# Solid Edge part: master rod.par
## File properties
Author: Deepak Maini
Template: normal.par
Last saved by: Robert a Rhodes jr
Revision: 7
Application: Solid Edge
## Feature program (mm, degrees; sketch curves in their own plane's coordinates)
sketch for "unnamed Protrusion 1" #1 plane through (0, 0, 0) normal (0, 0, 1) x-axis (1, 0, 0)
  circle centre (-104.4884, 26) radius 5
sketch for "unnamed Protrusion 1" #2 plane through (0, 0, 0) normal (0, 0, 1) x-axis (1, 0, 0)
  circle centre (-50.4884, 43) radius 5
sketch for "unnamed Protrusion 1" #3 plane through (0, 0, 0) normal (0, 0, 1) x-axis (1, 0, 0)
  circle centre (-104.4884, -26) radius 5
sketch for "unnamed Protrusion 1" #4 plane through (0, 0, 0) normal (0, 0, 1) x-axis (1, 0, 0)
  circle centre (-50.4884, -43) radius 5
sketch for "unnamed Protrusion 1" #5 plane through (0, 0, 0) normal (0, 0, 1) x-axis (1, 0, 0)
  arc centre (-185.4143, 0) radius 72 from (-116.8653, -22.0235) to (-116.8653, 22.0235) ccw
  arc centre (-104.4884, 26) radius 13 from (-116.8653, 22.0235) to (-104.0399, 38.9923) cw
  arc centre (-101.5558, 110.9494) radius 72 from (-104.0399, 38.9923) to (-58.2987, 53.3923) ccw
  arc centre (-50.4884, 43) radius 13 from (-58.2987, 53.3923) to (-39.1844, 49.4202) cw
  arc centre (23.4225, 84.9783) radius 72 from (-39.1844, 49.4202) to (21.6546, 13) ccw
  line (21.6546, 13) -> (184.5116, 9)
  line (184.5116, 9) -> (184.5116, -9)
  line (184.5116, -9) -> (21.6546, -13)
  arc centre (23.4225, -84.9783) radius 72 from (-39.1844, -49.4202) to (21.6546, -13) cw
  arc centre (-50.4884, -43) radius 13 from (-58.2987, -53.3923) to (-39.1844, -49.4202) ccw
  arc centre (-101.5558, -110.9494) radius 72 from (-104.0399, -38.9923) to (-58.2987, -53.3923) cw
  arc centre (-104.4884, -26) radius 13 from (-116.8653, -22.0235) to (-104.0399, -38.9923) ccw
  dimension (linear) = 104.4884
  dimension (linear) = 104.4884
  dimension (linear) = 21.6546
extrude "unnamed Protrusion 1" add finite 40 symmetric
sketch for "unnamed Protrusion 2" plane through (0, 0, 0) normal (0, 0, 1) x-axis (1, 0, 0)
  circle centre (-65.4884, 0) radius 31.5
extrude "unnamed Protrusion 2" add finite 70 symmetric
sketch for "unnamed Cutout 1" plane through (-65.4884, 0, 35) normal (0, 0, 1) x-axis (1, 0, 0)
  circle centre (0, 0) radius 26
extrude "unnamed Cutout 1" cut through along -normal
sketch for "unnamed Cutout 2" plane through (0, 0, 0) normal (0, 0, 1) x-axis (1, 0, 0)
  arc centre (-185.4143, 0) radius 72 from (-116.8653, -22.0235) to (-116.8653, 22.0235) ccw
  arc centre (-104.4884, 26) radius 13 from (-116.8653, 22.0235) to (-104.0399, 38.9923) cw
  arc centre (-101.5558, 110.9494) radius 72 from (-104.0399, 38.9923) to (-58.2987, 53.3923) ccw
  arc centre (-50.4884, 43) radius 13 from (-58.2987, 53.3923) to (-39.1844, 49.4202) cw
  arc centre (23.4225, 84.9783) radius 72 from (-39.1844, 49.4202) to (21.6408, 13.0003) ccw
  arc centre (26.7635, 219.9485) radius 207.0115 from (21.6408, 13.0003) to (-53.3048, 29.0484) cw
  arc centre (-65.4884, 0) radius 31.5 from (-53.3064, -29.0491) to (-53.3048, 29.0484) cw
  arc centre (26.7787, -220.0192) radius 207.0826 from (21.6337, -13.0005) to (-53.3064, -29.0491) ccw
  arc centre (23.4225, -84.9783) radius 72 from (21.6337, -13.0005) to (-39.1844, -49.4202) ccw
  arc centre (-50.4884, -43) radius 13 from (-39.1844, -49.4202) to (-58.2987, -53.3923) cw
  arc centre (-101.5558, -110.9494) radius 72 from (-58.2987, -53.3923) to (-104.0399, -38.9923) ccw
  arc centre (-104.4884, -26) radius 13 from (-104.0399, -38.9923) to (-116.8653, -22.0235) cw
extrude "unnamed Cutout 2" cut finite 28 symmetric
sketch for "unnamed Cutout 3" plane through (0, 0, 0) normal (0, -1, 0) x-axis (1, 0, 0)
  line (44.7709, 14.1242) -> (184.5116, 9.0608)
  arc centre (52.2023, 91.7693) radius 78 from (21.6546, 20) to (44.7709, 14.1242) ccw
  line (20.7865, 38.9081) -> (21.6546, 20)
  line (184.5116, 38.9081) -> (20.7865, 38.9081)
  line (184.5116, 9.0608) -> (184.5116, 38.9081)
extrude "unnamed Cutout 3" cut finite 355.6 symmetric
mirror "unnamed Mirror 1" of "unnamed Cutout 3" about plane through (0, 0, 0) normal (0, 0, 1)
extrude "unnamed Cutout 4" cut finite 355.6 symmetric
sketch for "unnamed Protrusion 3" plane through (0, 0, 0) normal (0, 0, 1) x-axis (1, 0, 0)
  circle centre (184.5116, 0) radius 17.5
extrude "unnamed Protrusion 3" add finite 42 symmetric
sketch for "unnamed Cutout 5" plane through (184.5116, 0, 21) normal (0, 0, 1) x-axis (1, 0, 0)
  circle centre (0, 0) radius 12
extrude "unnamed Cutout 5" cut through along -normal
sketch for "unnamed Cutout 6" plane through (0, 0, 0) normal (0, 0, 1) x-axis (1, 0, 0)
  line (0.4837, -6) -> (150.4837, -6)
  arc centre (0.4837, 0) radius 6 from (0.4837, 6) to (0.4837, -6) ccw
  line (150.4837, 6) -> (0.4837, 6)
  arc centre (150.4837, 0) radius 6 from (150.4837, 6) to (150.4837, -6) cw
extrude "unnamed Cutout 6" cut finite 222.25 symmetric
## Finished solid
Body 1: solid body, 52 faces, 130 edges, 68 vertices.
  Faces by surface: cylinder 38, plane 14
  Edges by curve: circle 74, line 48, ellipse 8
Bounding box of the edges (mm): 319.500 x 112.000 x 70.000, from (-117.4884, -56, -35) to (202.0116, 56, 35).
Cylindrical faces by radius (mm): R5 x8, R6 x2, R12 x1, R13 x8, R17.5 x1, R26 x1, R31.5 x3, R72 x8, R78 x4, R207.0115 x1, R207.0826 x1
Planar faces by outward normal: +y 1, +z 4, -y 1, -z 4, oblique 4
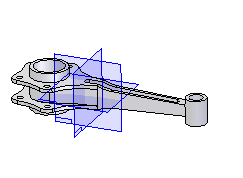
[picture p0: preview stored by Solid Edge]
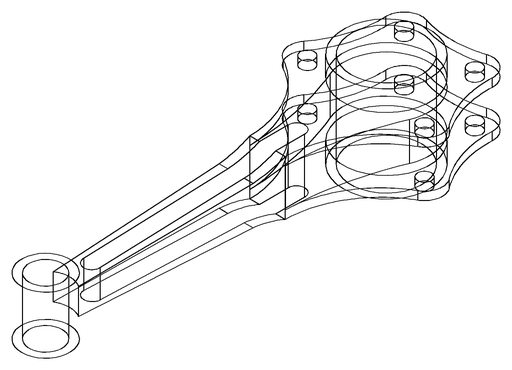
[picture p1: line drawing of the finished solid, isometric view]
